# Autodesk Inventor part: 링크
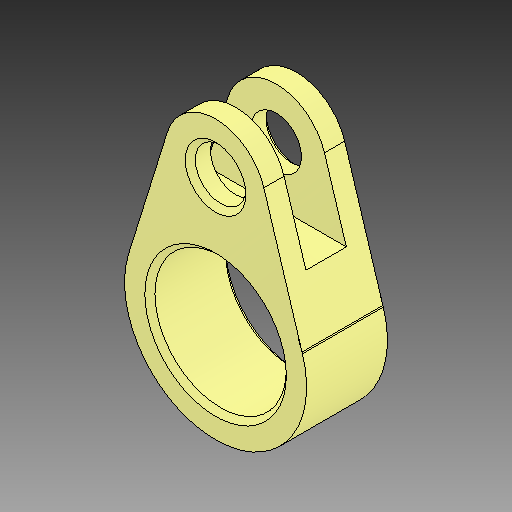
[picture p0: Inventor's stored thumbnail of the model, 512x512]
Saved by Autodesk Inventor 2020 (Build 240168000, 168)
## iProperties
Created: 2024-08
Part Number: 링크
Material: 강철, 연강
Document SubType Name: Modeling
Designer: 1강의실14
Density: 7.85 g/cm^3
Appearance: 기본값
Author: jhkim
Sending System: Autodesk Inventor 2025
Preprocessor: ST-DEVELOPER v20
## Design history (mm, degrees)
feature "솔리드1"
node "솔리드2"
